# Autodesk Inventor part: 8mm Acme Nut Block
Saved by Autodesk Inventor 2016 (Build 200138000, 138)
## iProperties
Created: 2016-01
Part Number: 8mm Acme Nut Block
Material: Generic
Document SubType Name: Modeling
Designer: John
Density: 1 g/cm^3
Appearance: Default
Author: John
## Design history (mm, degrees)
feature "CUT-EXTRUDE4"
body "Solid1"
